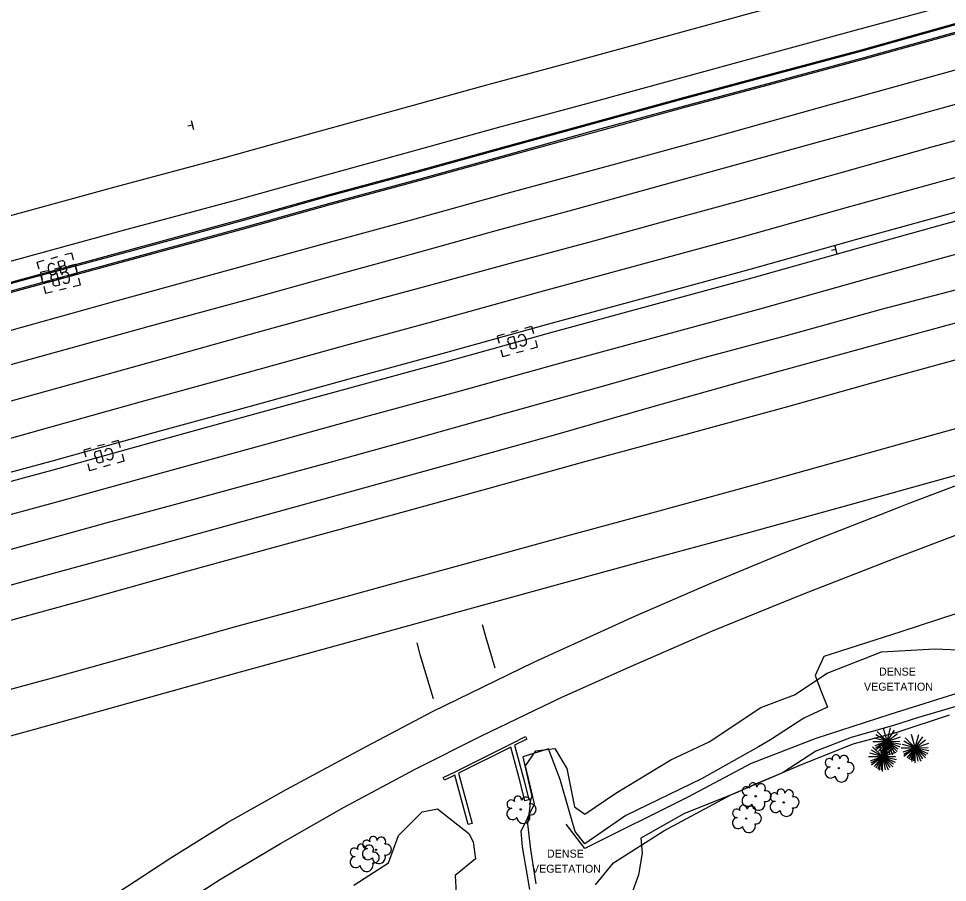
# Model space of a CAD drawing. Extents: x 2129547 to 2134906, y 657330 to 659734.
# Drawn here: x 2132780.8 to 2133105.8, y 658466.7 to 658769 of the extents above; entities that cross this region are included whole.
import ezdxf

# ---------------------------------------------------------------- set-up
doc = ezdxf.new("R2010")
doc.units = 0
for name, color, linetype in [('Default', 7, 'Continuous'), ('DR_X_Cells', 7, 'Continuous'), ('DR_X_Culvert', 7, 'Continuous'), ('DR_X_Drainage_Area', 7, 'Continuous'), ('PM_X_Edge_Line', 7, 'Continuous'), ('PM_X_Lane_Line', 7, 'Continuous'), ('PV_X_Curb', 7, 'Continuous'), ('PV_X_EOP2', 7, 'Continuous'), ('PV_X_Shoulder', 7, 'Continuous'), ('RD_X_Concrete_Barrier', 7, 'Continuous'), ('RD_X_Fence', 7, 'Continuous'), ('RD_X_Misc_Items', 7, 'Continuous'), ('SN_X_Public', 7, 'Continuous'), ('VG_X_Cells', 7, 'Continuous'), ('VG_X_Text', 7, 'Continuous'), ('VG_X_Tree_Line_Lt', 7, 'Continuous')]:
    doc.layers.add(name, color=color, linetype=linetype)

# ---------------------------------------------------------------- blocks, each defined once
blk = doc.blocks.new('SGN1P')
at = {"layer": 'SN_X_Public'}
for p, q in [((0, 0), (-0.02032, 0)), ((0, 0.02032), (0, -0.02032))]:
    blk.add_line(p, q, dxfattribs=at)
blk = doc.blocks.new('TREE')
at = {"layer": 'VG_X_Cells'}
blk.add_circle((0, 0), 0.00305, dxfattribs=at)
for centre, radius, start, end in [((-0.042, 0.0237), 0.0187, 39.0625, 279.5412), ((-0.0125, 0.0428), 0.0167, 354.0047, 205.9741), ((0.0232, 0.0359), 0.0197, 323.83, 165.0376), ((-0.0362, -0.0197), 0.0251, 96.1722, 320.5737), ((0.0439, 0.0005), 0.0243, 259.1453, 101.4596), ((0.012, -0.0331), 0.029, 184.9476, 19.4572)]:
    blk.add_arc(centre, radius, start, end, dxfattribs=at)
blk = doc.blocks.new('ETREE')
at = {"layer": 'VG_X_Cells'}
for p, q in [((0, 0), (-0.0443, 0.0443)), ((0, 0), (-0.0157, 0.0586)), ((0, 0), (0.016, 0.0597)), ((0, 0), (0.0337, 0.0493)), ((-0.0627, 0), (0, 0)), ((0, 0), (-0.056, 0.015)), ((0, 0), (-0.0545, -0.0198)), ((0, 0), (-0.0506, -0.029)), ((0, 0), (-0.0496, 0.0292)), ((0, 0), (-0.0496, -0.038)), ((0, 0), (-0.0374, -0.044)), ((0, 0), (-0.0294, -0.051)), ((0, 0), (-0.0211, -0.0551)), ((0, 0), (-0.016, -0.0617)), ((0, 0), (-0.0069, -0.0583)), ((0, 0), (0.0464, 0.0356)), ((0, 0), (0.0602, 0.0204)), ((0, 0), (0.0573, 0.0012)), ((0, -0.0665), (0, 0)), ((0, 0), (0.0117, -0.0589)), ((0, 0), (0.0246, -0.0593)), ((0, 0), (0.0322, -0.0482)), ((0, 0), (0.0456, -0.0447)), ((0, 0), (0.0485, -0.0324)), ((0, 0), (0.0567, -0.0247)), ((0, 0), (0.0613, -0.0122))]:
    blk.add_line(p, q, dxfattribs=at)
blk = doc.blocks.new('POINT_DISPLAY')
at = {"layer": 'Default'}
blk.add_line((0, 0), (0, 0), dxfattribs=at)
blk = doc.blocks.new('GCB-X')
at = {"layer": 'Default'}
for p, q in [((-0.0317, 0.019), (-0.019, 0.019)), ((-0.0317, 0.0063), (-0.0317, 0.019)), ((-0.0063, 0.019), (0.0063, 0.019)), ((0.019, 0.019), (0.0317, 0.019)), ((0.0317, 0.0063), (0.0317, 0.019)), ((0.0034, 0.0007), (0.0124, 0.0007)), ((-0.0317, -0.019), (-0.0317, -0.0063)), ((0.0317, -0.019), (0.0317, -0.0063)), ((-0.0317, -0.019), (-0.019, -0.019)), ((-0.0063, -0.019), (0.0063, -0.019)), ((0.019, -0.019), (0.0317, -0.019))]:
    blk.add_line(p, q, dxfattribs=at)
blk.add_lwpolyline([(0.0116, 0.0099), (0.0034, 0.0099), (0.0034, -0.0104), (0.0124, -0.0104)], dxfattribs=at)
for centre, radius, start, end in [((0.0071, 0), 0.0233, 164.8107, 195.1893), ((-0.0094, 0.0037), 0.00645, 21.5603, 158.4397), ((0.0101, 0.0051), 0.00501, 296.8207, 73.0013), ((0.0101, -0.0049), 0.00597, 292.0547, 67.9453), ((-0.0094, -0.0037), 0.00645, 201.5603, 338.4397)]:
    blk.add_arc(centre, radius, start, end, dxfattribs=at)
for p in [(0, 0.019), (0, 0.019), (-0.0317, 0), (0, 0), (0, 0), (0, 0), (0.0317, 0), (0, -0.019), (0, -0.019)]:
    blk.add_blockref('POINT_DISPLAY', p, dxfattribs=at)

msp = doc.modelspace()

# ---------------------------------------------------------------- linework, layer by layer
at = {"layer": 'DR_X_Culvert'}
msp.add_lwpolyline([(2132929.39, 658503.41), (2132933.6, 658505.43), (2132953.62, 658515.46), (2132958.15, 658517.74), (2132958.6, 658516.84), (2132954.34, 658514.7), (2132957.72, 658502.26), (2132959.33, 658495.58), (2132957.87, 658495.23), (2132956.26, 658501.89), (2132952.98, 658514.02), (2132934.77, 658504.91), (2132939.5, 658487.3), (2132938.05, 658486.91), (2132933.4, 658504.23), (2132929.83, 658502.51)], close=True, dxfattribs=at)
at = {"layer": 'DR_X_Drainage_Area'}
for points in [[(2132947.6, 658541.68), (2132944.37, 658552.33), (2132943.08, 658556.86)], [(2132926.02, 658530.95), (2132921.47, 658546), (2132920.28, 658550.55)]]:
    msp.add_lwpolyline(points, dxfattribs=at)
at = {"layer": 'PM_X_Edge_Line'}
for points in [[(2133352.86, 658840.89), (2133312.19, 658829.94), (2133247.7, 658812.58), (2133183.7, 658795.08), (2133146.25, 658784.96), (2133107.51, 658774.1), (2133073.85, 658764.93), (2133041.79, 658756.19), (2133011.05, 658747.8), (2132979.94, 658739.33), (2132948.72, 658730.94), (2132917.57, 658722.29), (2132887.16, 658713.87), (2132857, 658705.5), (2132818.68, 658695.21), (2132780.46, 658684.71), (2132740.98, 658673.64), (2132705.56, 658663.7), (2132666.4, 658652.81), (2132631.49, 658643.36), (2132595.52, 658633.47), (2132567.08, 658625.72), (2132529.28, 658615.18)], [(2132528.76, 658591.3), (2132572.65, 658603.2), (2132602.55, 658611.29), (2132644.66, 658622.9), (2132678.49, 658632.23), (2132709.33, 658640.79), (2132742.09, 658649.84), (2132779.08, 658660.22), (2132814.09, 658669.97), (2132851.16, 658680.16), (2132885.72, 658689.68), (2132917.4, 658698.33), (2132953.49, 658708.38), (2132988.45, 658717.87), (2133023.88, 658727.48), (2133061.03, 658737.93), (2133108.53, 658751.04), (2133150.67, 658762.63), (2133188.97, 658773.11), (2133222.93, 658782.47), (2133258.8, 658792.21), (2133300.07, 658803.6), (2133337.89, 658813.96)], [(2132751.82, 658614.87), (2132788.85, 658625.26), (2132823.77, 658634.98), (2132860.8, 658645.16), (2132895.33, 658654.67), (2132927.05, 658663.34), (2132963.11, 658673.38), (2132997.96, 658682.83), (2133033.55, 658692.49), (2133070.77, 658702.96), (2133118.17, 658716.04), (2133160.28, 658727.62), (2133198.58, 658738.11), (2133232.5, 658747.46), (2133268.38, 658757.19), (2133309.7, 658768.6), (2133347.5, 658778.96)], [(2132529.63, 658631.32), (2132552.22, 658637.55), (2132563.39, 658640.65), (2132591.42, 658648.37), (2132627.43, 658658.26), (2132662.31, 658667.71), (2132701.4, 658678.58), (2132736.81, 658688.52), (2132776.33, 658699.59), (2132814.63, 658710.12), (2132852.93, 658720.4), (2132883.03, 658728.76), (2132913.44, 658737.18), (2132944.65, 658745.84), (2132975.91, 658754.24), (2133006.99, 658762.7), (2133037.72, 658771.1)], [(2133316.59, 658743.53), (2133275.25, 658732.12), (2133239.36, 658722.38), (2133205.47, 658713.04), (2133167.16, 658702.55), (2133125.07, 658690.98), (2133077.75, 658677.91), (2133040.47, 658667.43), (2133004.77, 658657.74), (2132970.01, 658648.31), (2132933.96, 658638.28), (2132902.2, 658629.6), (2132867.7, 658620.1), (2132830.71, 658609.93), (2132795.85, 658600.22), (2132736.97, 658584.29), (2132686.86, 658570.47), (2132647.78, 658559.73), (2132616.38, 658551.02), (2132587.48, 658543.23), (2132543.98, 658531.22), (2132527.44, 658526.61)], [(2132526.73, 658488.71), (2132530.21, 658489.67), (2132569.63, 658500.53), (2132596.17, 658508.1), (2132621.44, 658515.22), (2132661.75, 658526.36), (2132698.15, 658536.48), (2132732.1, 658545.81), (2132769.52, 658556.2), (2132805.25, 658565.98), (2132840.18, 658575.71), (2132877.13, 658585.87), (2132911.6, 658595.36), (2132943.4, 658604.05), (2132979.41, 658614.08), (2133014.06, 658623.48), (2133049.93, 658633.21), (2133087.28, 658643.72), (2133134.5, 658656.75), (2133176.55, 658668.31), (2133214.88, 658678.81), (2133247.85, 658688.07), (2133283.96, 658698.16), (2133325.94, 658709.93)], [(2133330.15, 658689.11), (2133297.63, 658679.74), (2133266.56, 658670.62), (2133226.79, 658659.12), (2133197.42, 658650.62), (2133167.14, 658641.9), (2133134.04, 658632.57), (2133102.68, 658623.78), (2133072.24, 658615.25), (2133037.61, 658605.58), (2133003.5, 658596.32), (2132971.17, 658587.53), (2132944.96, 658580.31), (2132910.44, 658570.81), (2132883.46, 658563.38), (2132856.23, 658556.06), (2132824.38, 658546.99), (2132792.59, 658538.19), (2132761.91, 658529.84)], [(2132780.42, 658417.85), (2132794.53, 658428.85), (2132808.02, 658438.8), (2132828.29, 658452.89), (2132851.51, 658467.84), (2132872.43, 658480.36), (2132894.67, 658493.03), (2132919.61, 658506.34), (2132942.8, 658518.03), (2132970.58, 658531.41), (2132994.65, 658542.18), (2133023.55, 658554.71), (2133055.17, 658567.57), (2133087.49, 658580.23), (2133114.79, 658590.55), (2133143.49, 658600.71), (2133168.31, 658608.81), (2133196.23, 658617.63), (2133226.14, 658626.84), (2133262.28, 658638.19), (2133300.81, 658650.13), (2133340.17, 658662.31)], [(2133158.51, 658623.08), (2133137.32, 658617.18), (2133107.75, 658608.87), (2133069.12, 658598.17), (2133036.14, 658589.08), (2133001.62, 658579.74), (2132965.01, 658569.7), (2132930.32, 658560.06), (2132893.98, 658550.04), (2132857.01, 658539.9), (2132824.05, 658530.67), (2132784.28, 658519.67), (2132746.13, 658509.23), (2132706.06, 658498.15), (2132669.95, 658488.27), (2132635.09, 658478.56), (2132605.57, 658470.07), (2132586.69, 658464.73), (2132544.05, 658452.96), (2132525.87, 658448)], [(2132778.88, 658436.51), (2132797.28, 658450.31), (2132815.53, 658463.15), (2132834.09, 658475.32), (2132853.88, 658487.67), (2132874.62, 658499.37), (2132902.61, 658514.38), (2132925.64, 658526.53), (2132961.12, 658543.72), (2132996.4, 658559.86), (2133023.56, 658571.6), (2133058.45, 658586.09), (2133087.14, 658597.32), (2133091.83, 658599.15), (2133110.89, 658606.44), (2133134.83, 658615.24), (2133158.51, 658623.08)]]:
    msp.add_lwpolyline(points, dxfattribs=at)
at = {"layer": 'PM_X_Lane_Line'}
for points in [[(2132770.46, 658645.83), (2132797.06, 658653.26), (2132828.19, 658661.83), (2132861.38, 658670.87), (2132890.6, 658678.93), (2132920.35, 658687.14), (2132947.85, 658694.81), (2132974.67, 658702.08), (2133006.64, 658710.96), (2133034.51, 658718.68), (2133060.36, 658725.76), (2133088.12, 658733.33), (2133112.45, 658740.12), (2133143.94, 658748.72), (2133173.17, 658756.72), (2133202.56, 658765), (2133233.48, 658773.28)], [(2133270.18, 658770.37), (2133241.97, 658762.79), (2133214.5, 658755.19), (2133189.65, 658748.43), (2133161.27, 658740.52), (2133133.55, 658733.02), (2133100.64, 658724.1), (2133069.76, 658715.44), (2133037.24, 658706.34), (2133009.32, 658698.73), (2132981.91, 658691.14), (2132953.6, 658683.48), (2132924.09, 658675.45), (2132896.78, 658668.12), (2132864.32, 658659.21), (2132830.55, 658649.67), (2132796.16, 658640.09), (2132761.23, 658630.43)], [(2133319.94, 658732.31), (2133288.5, 658723.61), (2133259.3, 658715.66), (2133234.36, 658708.83), (2133202.83, 658700.05), (2133174.08, 658691.94), (2133140.33, 658682.75), (2133108.95, 658674.06), (2133082.6, 658667.15), (2133049.4, 658658.04), (2133018.8, 658649.85), (2132984.92, 658640.29), (2132949.38, 658630.35), (2132919.99, 658622.07), (2132890.94, 658613.99), (2132858.31, 658605.1), (2132836.54, 658599.14), (2132811.38, 658592.48), (2132777.26, 658582.97)], [(2133330.22, 658723.85), (2133298.5, 658714.96), (2133261.81, 658705.07), (2133227.15, 658695.47), (2133194.29, 658686.12), (2133154.93, 658675.36), (2133115.86, 658664.39), (2133078.14, 658654.11), (2133038.27, 658643.16), (2133002.28, 658632.99), (2132968.65, 658623.33), (2132933.53, 658613.55), (2132899.33, 658604.14), (2132864.71, 658594.55), (2132827.99, 658584.36), (2132790.39, 658574.06), (2132761.16, 658566.05), (2132724.86, 658555.97), (2132689.68, 658546.19), (2132656.96, 658537.15), (2132624.97, 658528.2), (2132593.37, 658519.4), (2132560.89, 658510.33), (2132526.97, 658501.13)]]:
    msp.add_lwpolyline(points, dxfattribs=at)
at = {"layer": 'PV_X_Curb'}
for points in [[(2133354.62, 658834.11), (2133313.99, 658822.98), (2133249.15, 658805.18), (2133186.51, 658788.1), (2133148.3, 658777.86), (2133109.44, 658767.05), (2133075.85, 658757.65), (2133043.52, 658748.97), (2133012.69, 658740.69), (2132981.33, 658732.09), (2132950.79, 658723.65), (2132920.09, 658715.1), (2132889.35, 658706.83), (2132858.99, 658698.27), (2132820.58, 658687.77), (2132782.52, 658677.48), (2132742.93, 658666.63), (2132707.48, 658656.83), (2132668.28, 658645.96), (2132633.36, 658636.51), (2132602.69, 658628.08)], [(2133355.25, 658831.69), (2133314.65, 658820.57), (2133249.81, 658802.77), (2133187.16, 658785.68), (2133148.96, 658775.45), (2133110.11, 658764.65), (2133076.51, 658755.24), (2133044.17, 658746.56), (2133013.34, 658738.28), (2132981.99, 658729.68), (2132951.45, 658721.24), (2132920.75, 658712.69), (2132890.01, 658704.42), (2132859.66, 658695.87), (2132821.24, 658685.36), (2132783.18, 658675.06), (2132743.6, 658664.22), (2132708.14, 658654.42), (2132668.94, 658643.55), (2132634.02, 658634.09), (2132603.1, 658625.87)]]:
    msp.add_lwpolyline(points, dxfattribs=at)
at = {"layer": 'PV_X_EOP2'}
for points in [[(2133352.86, 658840.89), (2133312.19, 658829.94), (2133247.7, 658812.58), (2133183.7, 658795.08), (2133146.25, 658784.96), (2133107.51, 658774.1), (2133073.85, 658764.93), (2133041.79, 658756.19), (2133011.05, 658747.8), (2132979.94, 658739.33), (2132948.72, 658730.94), (2132917.57, 658722.29), (2132887.16, 658713.87), (2132857, 658705.5), (2132818.68, 658695.21), (2132780.46, 658684.71), (2132740.98, 658673.64), (2132705.56, 658663.7), (2132666.4, 658652.81), (2132631.49, 658643.36), (2132595.52, 658633.47), (2132567.08, 658625.72), (2132529.28, 658615.18)], [(2132529.63, 658631.32), (2132552.22, 658637.55), (2132563.39, 658640.65), (2132591.42, 658648.37), (2132627.43, 658658.26), (2132662.31, 658667.71), (2132701.4, 658678.58), (2132736.81, 658688.52), (2132776.33, 658699.59), (2132814.63, 658710.12), (2132852.93, 658720.4), (2132883.03, 658728.76), (2132913.44, 658737.18), (2132944.65, 658745.84), (2132975.91, 658754.24), (2133006.99, 658762.7), (2133037.72, 658771.1), (2133069.79, 658779.83), (2133103.39, 658788.99), (2133142.1, 658799.84), (2133179.64, 658810.26), (2133239.99, 658826.51)], [(2132528.76, 658591.3), (2132572.65, 658603.2), (2132602.55, 658611.29), (2132644.66, 658622.9), (2132678.49, 658632.23), (2132709.33, 658640.79), (2132742.09, 658649.84), (2132779.08, 658660.22), (2132814.09, 658669.97), (2132851.16, 658680.16), (2132885.72, 658689.68), (2132917.4, 658698.33), (2132953.49, 658708.38), (2132988.45, 658717.87), (2133023.88, 658727.48), (2133061.03, 658737.93), (2133108.53, 658751.04), (2133150.67, 658762.63), (2133188.97, 658773.11), (2133222.93, 658782.47), (2133258.8, 658792.21), (2133300.07, 658803.6), (2133337.89, 658813.96)], [(2132751.82, 658614.87), (2132788.85, 658625.26), (2132823.77, 658634.98), (2132860.8, 658645.16), (2132895.33, 658654.67), (2132927.05, 658663.34), (2132963.11, 658673.38), (2132997.96, 658682.83), (2133033.55, 658692.49), (2133070.77, 658702.96), (2133118.17, 658716.04), (2133160.28, 658727.62), (2133198.58, 658738.11), (2133232.5, 658747.46), (2133268.38, 658757.19), (2133309.7, 658768.6), (2133347.5, 658778.96)], [(2133316.59, 658743.53), (2133275.25, 658732.12), (2133239.36, 658722.38), (2133205.47, 658713.04), (2133167.16, 658702.55), (2133125.07, 658690.98), (2133077.75, 658677.91), (2133040.47, 658667.43), (2133004.77, 658657.74), (2132970.01, 658648.31), (2132933.96, 658638.28), (2132902.2, 658629.6), (2132867.7, 658620.1), (2132830.71, 658609.93), (2132795.85, 658600.22), (2132736.97, 658584.29), (2132686.86, 658570.47), (2132647.78, 658559.73), (2132616.38, 658551.02), (2132587.48, 658543.23), (2132543.98, 658531.22), (2132527.44, 658526.61)], [(2132526.73, 658488.71), (2132530.21, 658489.67), (2132569.63, 658500.53), (2132596.17, 658508.1), (2132621.44, 658515.22), (2132661.75, 658526.36), (2132698.15, 658536.48), (2132732.1, 658545.81), (2132769.52, 658556.2), (2132805.25, 658565.98), (2132840.18, 658575.71), (2132877.13, 658585.87), (2132911.6, 658595.36), (2132943.4, 658604.05), (2132979.41, 658614.08), (2133014.06, 658623.48), (2133049.93, 658633.21), (2133087.28, 658643.72), (2133134.5, 658656.75), (2133176.55, 658668.31), (2133214.88, 658678.81), (2133247.85, 658688.07), (2133283.96, 658698.16), (2133325.94, 658709.93)], [(2133330.15, 658689.11), (2133297.63, 658679.74), (2133266.56, 658670.62), (2133226.79, 658659.12), (2133197.42, 658650.62), (2133167.14, 658641.9), (2133134.04, 658632.57), (2133102.68, 658623.78), (2133072.24, 658615.25), (2133037.61, 658605.58), (2133003.5, 658596.32), (2132971.17, 658587.53), (2132944.96, 658580.31), (2132910.44, 658570.81), (2132883.46, 658563.38), (2132856.23, 658556.06), (2132824.38, 658546.99), (2132792.59, 658538.19), (2132761.91, 658529.84)]]:
    msp.add_lwpolyline(points, dxfattribs=at)
at = {"layer": 'PV_X_Shoulder'}
for points in [[(2132602.56, 658628.56), (2132633.23, 658636.99), (2132668.15, 658646.45), (2132707.34, 658657.31), (2132742.8, 658667.11), (2132782.39, 658677.96), (2132820.45, 658688.26), (2132858.86, 658698.76), (2132889.22, 658707.31), (2132919.96, 658715.58), (2132950.65, 658724.13), (2132981.19, 658732.57), (2133012.56, 658741.17), (2133043.39, 658749.45), (2133075.72, 658758.13), (2133109.31, 658767.54), (2133148.17, 658778.35), (2133186.38, 658788.58), (2133249.02, 658805.67), (2133313.86, 658823.46), (2133354.5, 658834.6)], [(2133355.38, 658831.21), (2133314.78, 658820.09), (2133249.94, 658802.29), (2133187.29, 658785.2), (2133149.09, 658774.97), (2133110.25, 658764.16), (2133076.65, 658754.76), (2133044.3, 658746.07), (2133013.47, 658737.79), (2132982.12, 658729.2), (2132951.59, 658720.76), (2132920.88, 658712.21), (2132890.15, 658703.93), (2132859.8, 658695.38), (2132821.37, 658684.88), (2132783.31, 658674.58), (2132743.73, 658663.74), (2132708.28, 658653.94), (2132669.07, 658643.07), (2132634.15, 658633.61), (2132603.23, 658625.39)]]:
    msp.add_lwpolyline(points, dxfattribs=at)
at = {"layer": 'RD_X_Concrete_Barrier'}
for points in [[(2132733.99, 658595.19), (2132792.86, 658611.11), (2132827.69, 658620.82), (2132864.7, 658630.99), (2132899.22, 658640.5), (2132930.96, 658649.17), (2132967.01, 658659.2), (2133001.81, 658668.65), (2133037.46, 658678.32), (2133074.72, 658688.8), (2133113.76, 658699.58), (2133132.75, 658704), (2133143.27, 658706.9), (2133162.3, 658712.93), (2133164.17, 658713.44), (2133202.48, 658723.94), (2133236.38, 658733.28), (2133272.26, 658743.02), (2133313.6, 658754.43), (2133351.4, 658764.78)], [(2133114.6, 658702.92), (2133073.91, 658691.69), (2133036.67, 658681.21), (2133001.02, 658671.54), (2132966.22, 658662.09), (2132930.16, 658652.06), (2132898.42, 658643.39), (2132863.91, 658633.88), (2132826.89, 658623.71), (2132792.07, 658614.01), (2132733.2, 658598.09), (2132728.03, 658596.66), (2132708.65, 658592.09), (2132698.07, 658589.17), (2132680.32, 658583.5), (2132643.98, 658573.52), (2132612.61, 658564.81), (2132584.03, 658557.2), (2132559.64, 658550.51), (2132527.73, 658542.1)]]:
    msp.add_lwpolyline(points, dxfattribs=at)
at = {"layer": 'RD_X_Fence'}
msp.add_lwpolyline([(2133409.37, 658623.24), (2133399.25, 658620.39), (2133396.55, 658620.65), (2133384.38, 658617.74), (2133380.03, 658615.44), (2133356.03, 658608.88), (2133325.9, 658600.19), (2133292.34, 658590.99), (2133278.32, 658586.5), (2133241.59, 658575.44), (2133201.86, 658562.85), (2133163.22, 658550.3), (2133136.09, 658541.38), (2133085.63, 658525.47), (2133059.75, 658517.07), (2133037.1, 658508.29), (2133014.93, 658496.51), (2132978.92, 658478.61), (2132972.42, 658487.07)], dxfattribs=at)
at = {"layer": 'RD_X_Misc_Items'}
for points in [[(2133109.38, 658560.89), (2133089.43, 658554.39), (2133062.55, 658545.8), (2133059.46, 658539.13), (2133061.52, 658533.91), (2133063.85, 658527.99), (2133055.48, 658524.22), (2133043.86, 658516.55), (2133039.66, 658514.18), (2133019.76, 658503), (2132993.31, 658490.12), (2132978.9, 658480.21), (2132975.57, 658484.51), (2132973.66, 658490.93), (2132970.26, 658502.7), (2132966.25, 658513.48), (2132957.22, 658510.68), (2132960.4, 658496.75), (2132959.88, 658495.58), (2132959.39, 658491.43), (2132958.81, 658487.15), (2132959.9, 658478.18), (2132961.42, 658468.45), (2132961.76, 658466.24)], [(2132982.66, 658465.8), (2132988.94, 658473.51), (2133006.56, 658484.72), (2133030.18, 658497.51), (2133053.92, 658507.66), (2133072.73, 658515.17), (2133088.23, 658519.27), (2133106.48, 658525.38)]]:
    msp.add_lwpolyline(points, dxfattribs=at)
at = {"layer": 'VG_X_Tree_Line_Lt'}
for points in [[(2132959.64, 658464.26), (2132957.08, 658479.1), (2132956.59, 658484.68), (2132961.28, 658494.21), (2132958.11, 658507.45), (2132961.77, 658512.74), (2132968.47, 658513.52), (2132972.6, 658506.53), (2132975.29, 658493.13), (2132978.94, 658490.6), (2132989.81, 658497.96), (2133008.97, 658509.63), (2133022.42, 658515.84), (2133040.43, 658527.92), (2133052.25, 658532.34), (2133063.67, 658539.87), (2133082.65, 658547.34), (2133101.39, 658548.42), (2133112.42, 658547.98)], [(2133118.64, 658531.19), (2133095.67, 658524.41), (2133086.88, 658521.61), (2133072.07, 658517.43), (2133059.67, 658512.61), (2133048.01, 658505.02), (2133037.27, 658500.52), (2133032.39, 658498.23), (2133013.51, 658490.68), (2132998.46, 658482.23), (2132998.98, 658476.96), (2132997.71, 658469.31), (2132994.49, 658460.63)], [(2132898.07, 658465.78), (2132910.24, 658473.54), (2132913.78, 658483.1), (2132921.96, 658491.45), (2132927.33, 658492.42), (2132938.29, 658483.87), (2132939.85, 658480.93), (2132940.62, 658474.95), (2132933.57, 658469.15), (2132933.87, 658462.79)]]:
    msp.add_lwpolyline(points, dxfattribs=at)

# ---------------------------------------------------------------- block references
at = {"layer": 'DR_X_Cells'}
for p, xscale, yscale, rotation in [((2132794.37, 658681.81), 196.85000000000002, 196.85, 15.17158944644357), ((2132795.44, 658677.92), 196.85, 196.85000000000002, -166.69975175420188), ((2132955.25, 658655.93), 196.85000000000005, 196.85000000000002, -164.4499396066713), ((2132810.67, 658616.07), 196.85, 196.85000000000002, -164.43420284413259)]:
    msp.add_blockref('GCB-X', p, dxfattribs=dict(at, xscale=xscale, yscale=yscale, rotation=rotation))
at = {"layer": 'SN_X_Public', "yscale": 78.74000000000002}
for p, xscale, rotation in [((2132841.63, 658731.76), 78.74000000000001, 14.214810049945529), ((2133066.7, 658688.25), 78.74000000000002, 14.076842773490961)]:
    msp.add_blockref('SGN1P', p, dxfattribs=dict(at, xscale=xscale, rotation=rotation))
at = {"layer": 'VG_X_Cells', "xscale": 78.74000000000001, "yscale": 78.74000000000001}
for name, p in [('ETREE', (2133084.63, 658516.05)), ('ETREE', (2133094.47, 658513.79)), ('ETREE', (2133083.07, 658510.71)), ('TREE', (2133067.77, 658506.72)), ('TREE', (2133038.71, 658496.84)), ('TREE', (2133048.52, 658494.69)), ('TREE', (2132956.47, 658492.22)), ('TREE', (2133035.35, 658489.05)), ('TREE', (2132905.9, 658478.14)), ('TREE', (2132901.62, 658475.39))]:
    msp.add_blockref(name, p, dxfattribs=at)

# ---------------------------------------------------------------- texts
at = {"layer": 'VG_X_Text'}
for s, p in [('DENSE', (2133081.83, 658539.07)), ('VEGETATION', (2133076.58, 658533.8)), ('DENSE', (2132965.66, 658475.37)), ('VEGETATION', (2132960.41, 658470.09))]:
    msp.add_text(s, height=2.8, dxfattribs=at).set_placement(p)

doc.saveas('drawing.dxf')
